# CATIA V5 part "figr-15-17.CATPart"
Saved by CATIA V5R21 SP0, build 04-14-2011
Part number: Part1
Bounding box of the stored display mesh (mm): x -46.56 to 46.56, y -26.965 to 25.965, z 0 to 40
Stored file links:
  D:\CATIA V5R21 E-RESOURCES\CATIA-V5R21\catia-v5r21-prt\c15-catia-v5r20-prt\c15-catia-v5r21-figr-15-17.CATPart
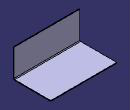
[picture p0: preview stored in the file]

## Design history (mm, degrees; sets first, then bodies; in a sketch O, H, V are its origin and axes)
SheetMetalParameters1: Thickness 1, BendRadius 1, KFactor 0.325257 {= log(min(100,max(20*SheetMetalParameters1.BendRadius,SheetMetalParameters1.Thickness)/SheetMetalParameters1.Thickness))/log(100)/2}, ReliefRadialLength 1, ReliefAxialLength 2, MinimumBendRadius 0
Body1 (main body)
  Sketch1 on xy-plane, origin (0, 0, 0), H (1, 0, 0), V (0, 1, 0)
    line L1 (-46.5596, 25.9646) -> (46.5596, 25.9646)
    line L2 (46.5596, 25.9646) -> (46.5596, -25.9646)
    line L3 (46.5596, -25.9646) -> (-46.5596, -25.9646)
    line L4 (-46.5596, -25.9646) -> (-46.5596, 25.9646)
    horizontal: L1 H, L3 H
    vertical: L2 V, L4 V
    symmetry: L1 L3 H, L4 L2 V
  Wall1: Thickness 1, Profile Sketch1
  d_NewWallOnEdge1: NewWallOnEdge_Edge edge [face of Wall1 | face of Wall1], NewWallOnEdge_Length 40, NewWallOnEdge_HeightLimitOffset 0, NewWallOnEdge_WidthOffset1 0, NewWallOnEdge_WidthOffset2 0, NewWallOnEdge_Angle 90, NewWallOnEdge_BendRadiusValue 1 {= SheetMetalParameters1.BendRadius}, NewWallOnEdge_BendTable SheetMetalParameters1, KFacteur 0.325257 {= log(min(100,max(20*d_NewWallOnEdge1.Radius,SheetMetalParameters1.Thickness)/SheetMetalParameters1.Thickness))/log(100)/2}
